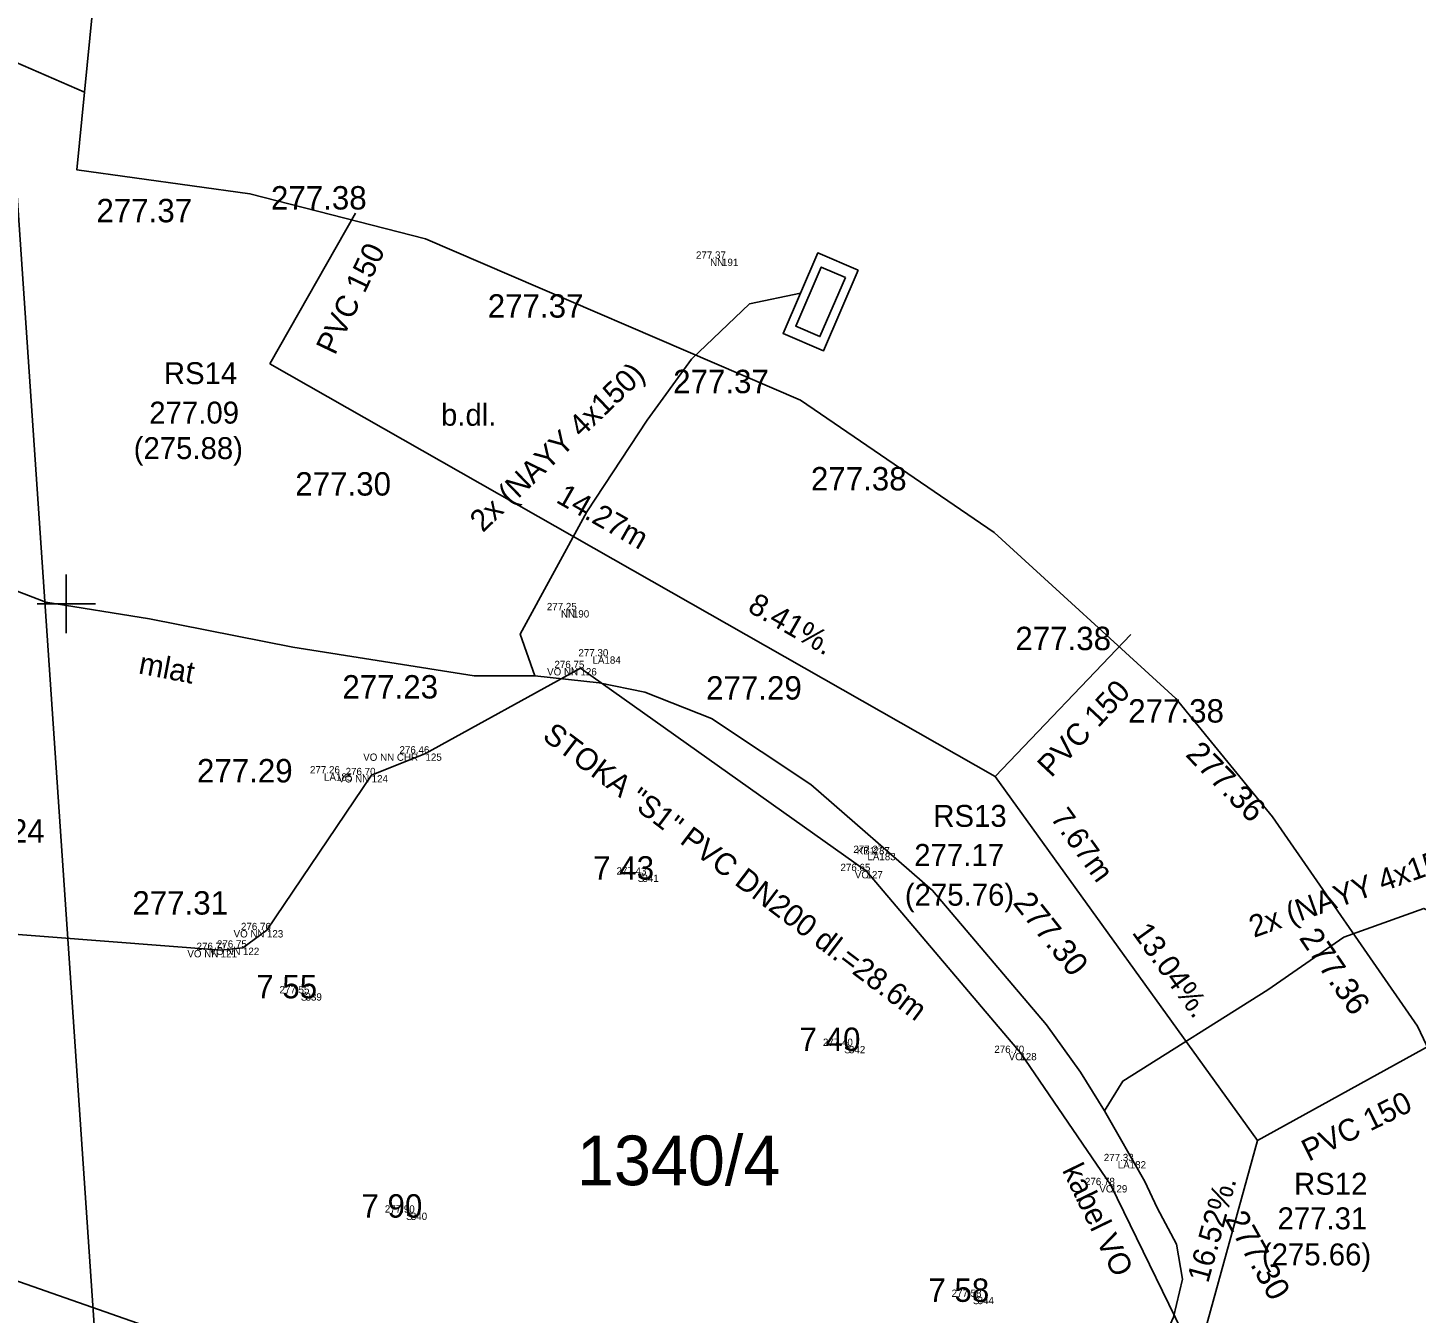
# Model space of a CAD drawing. Extents: x -601602 to -600882, y -1162594 to -1161950.
# Drawn here: x -601150.66 to -601126.92, y -1162087.13 to -1162065.15 of the extents above; entities that cross this region are included whole.
import ezdxf

# ---------------------------------------------------------------- set-up
doc = ezdxf.new("R2010")
doc.units = 0
for name, color, linetype in [('BODY', 7, 'Continuous'), ('BODY_CISLA', 7, 'Continuous'), ('BODY_KODY', 7, 'Continuous'), ('BODY_VYSKY_CELE', 7, 'Continuous'), ('G_TEXTY', 7, 'Continuous'), ('H_KOTY_VYSKOVE', 7, 'Continuous'), ('H_VYSKY_PREVZATE', 7, 'Continuous'), ('IS_EON_NN', 7, 'Continuous'), ('IS_KAN_SPLASKOVA', 7, 'Continuous'), ('IS_VO', 7, 'Continuous'), ('IS_VO_AREAL', 7, 'Continuous'), ('KN_Hranice parcel', 7, 'Continuous'), ('KN_Parcelní čísla', 7, 'Continuous'), ('X_SOUR_KRIZKY_SEVER', 7, 'Continuous')]:
    doc.layers.add(name, color=color, linetype=linetype)

# ---------------------------------------------------------------- blocks, each defined once
blk = doc.blocks.new('POINT_DISPLAY')
blk.add_line((0, 0), (0, 0))
blk = doc.blocks.new('132_9')
at = {"layer": 'IS_EON_NN'}
for points in [[(-1.5, 1.5), (1.5, 1.5), (1.5, 0), (-1.5, 0)], [(-1.1, 1.2), (1.1, 1.2), (1.1, 0.3), (-1.1, 0.3)]]:
    blk.add_lwpolyline(points, close=True, dxfattribs=at)

msp = doc.modelspace()

# ---------------------------------------------------------------- linework, layer by layer
at = {"layer": 'IS_EON_NN'}
for points in [[(-601156.45, -1162065.9), (-601156.46, -1162066.9), (-601156.74, -1162069.72), (-601157.04, -1162071.88), (-601156.69, -1162072.3), (-601155.65, -1162072.6), (-601154.16, -1162073.09), (-601152, -1162074.34), (-601150.35, -1162074.97), (-601148.58, -1162075.26), (-601146.13, -1162075.74), (-601143.03, -1162076.23), (-601141.99, -1162076.23)], [(-601141.99, -1162076.23), (-601142.24, -1162075.52), (-601141.1, -1162073.43), (-601140.07, -1162071.86), (-601139.31, -1162070.82), (-601138.32, -1162069.87), (-601137.45, -1162069.69)], [(-601132.25, -1162083.67), (-601132.66, -1162083.01), (-601133.24, -1162082.2), (-601135.19, -1162079.9), (-601137.27, -1162078.09), (-601138.97, -1162076.96), (-601140.11, -1162076.51), (-601140.89, -1162076.35), (-601141.99, -1162076.23)], [(-601132.25, -1162083.67), (-601131.94, -1162083.16), (-601129.46, -1162081.6), (-601128.16, -1162080.7), (-601126.79, -1162080.21), (-601125.98, -1162080.61)], [(-601132.25, -1162083.67), (-601131.56, -1162084.88), (-601131.35, -1162085.33), (-601131.02, -1162085.95), (-601130.92, -1162086.55), (-601131.07, -1162087.2), (-601132.61, -1162090.6), (-601133.2, -1162092.06), (-601133.29, -1162092.54), (-601133.09, -1162093.04), (-601132.66, -1162093.44), (-601128.6, -1162095.14), (-601128.04, -1162095.48)]]:
    msp.add_lwpolyline(points, dxfattribs=at)
at = {"layer": 'IS_KAN_SPLASKOVA'}
for p, q in [((-601146.52, -1162070.896), (-601145.055, -1162068.32)), ((-601131.802, -1162075.528), (-601134.119, -1162077.951)), ((-601126.484, -1162082.438), (-601129.637, -1162084.177))]:
    msp.add_line(p, q, dxfattribs=at)
msp.add_lwpolyline([(-601131.407, -1162090.599), (-601129.637, -1162084.177), (-601134.119, -1162077.951), (-601146.52, -1162070.896)], dxfattribs=at)
at = {"layer": 'IS_VO'}
msp.add_lwpolyline([(-601158.666, -1162083.84), (-601145.3, -1162088.52), (-601144.81, -1162089.24), (-601144.157, -1162088.925), (-601135.38, -1162092.04), (-601131.27, -1162093.86), (-601131.18, -1162093.85), (-601130.74, -1162094.17), (-601128.82, -1162095.1), (-601124.26, -1162100.28), (-601123.56, -1162100.82), (-601122.79, -1162101.34), (-601121.45, -1162102.28), (-601119.91, -1162102.84), (-601117.99, -1162103.55), (-601114.43, -1162104.44), (-601112.91, -1162104.68), (-601111.96, -1162104.83), (-601105.22, -1162106.94), (-601104.99, -1162107.32)], dxfattribs=at)
at = {"layer": 'IS_VO_AREAL'}
msp.add_lwpolyline([(-601151.27, -1162080.62), (-601147.36, -1162080.92), (-601146.98, -1162080.88), (-601146.57, -1162080.58), (-601144.78, -1162077.93), (-601143.86, -1162077.56), (-601141.21, -1162076.1), (-601136.32, -1162079.57), (-601133.69, -1162082.68), (-601132.14, -1162084.94), (-601130.6, -1162088.11), (-601130.19, -1162090.08), (-601131.12, -1162093.43), (-601131.18, -1162093.85)], dxfattribs=at)
at = {"layer": 'KN_Hranice parcel'}
for p in [(-601149.69, -1162066.25), (-601149.45, -1162088.38)]:
    msp.add_line(p, (-601151, -1162065.68), dxfattribs=at)
for points in [[(-601149.69, -1162066.25), (-601147.49, -1162043.97), (-601144.7, -1162044.26), (-601138.75, -1162045.48), (-601133.58, -1162047.15), (-601128.54, -1162049.35), (-601123.75, -1162052.06), (-601119.34, -1162055.16), (-601115.08, -1162058.98), (-601111.36, -1162063.04), (-601108.08, -1162067.46), (-601105.25, -1162072.3), (-601104.9, -1162073.07)], [(-601104.9, -1162073.07), (-601103.03, -1162077.23), (-601101.26, -1162082.55), (-601100.06, -1162087.92), (-601099.46, -1162093.3), (-601099.43, -1162099.35), (-601099.69, -1162102.16), (-601123.33, -1162099.81), (-601123.14, -1162096.25), (-601123.49, -1162092.41), (-601123.92, -1162089.87), (-601125.19, -1162085.83), (-601126.9, -1162082.22), (-601129.38, -1162078.64), (-601131.03, -1162076.62), (-601134.14, -1162073.78), (-601137.45, -1162071.52), (-601143.86, -1162068.76), (-601146.86, -1162067.99), (-601149.82, -1162067.58), (-601149.69, -1162066.25)]]:
    msp.add_lwpolyline(points, dxfattribs=at)
at = {"layer": 'X_SOUR_KRIZKY_SEVER'}
for p, q in [((-601150, -1162075.5), (-601150, -1162074.5)), ((-601150.5, -1162075), (-601149.5, -1162075))]:
    msp.add_line(p, q, dxfattribs=at)

# ---------------------------------------------------------------- block references
at = {"layer": 'BODY'}
for p in [(-601138.79, -1162069.1), (-601141.34, -1162075.11), (-601140.8, -1162075.9), (-601141.21, -1162076.1), (-601143.86, -1162077.56), (-601145.39, -1162077.9), (-601144.78, -1162077.93), (-601136.2, -1162079.16), (-601136.1, -1162079.26), (-601140.15, -1162079.63), (-601136.32, -1162079.57), (-601146.57, -1162080.58), (-601147.36, -1162080.92), (-601146.98, -1162080.88), (-601145.91, -1162081.66), (-601136.62, -1162082.56), (-601133.69, -1162082.68), (-601131.82, -1162084.53), (-601132.14, -1162084.94), (-601144.11, -1162085.41), (-601134.42, -1162086.85)]:
    msp.add_blockref('POINT_DISPLAY', p, dxfattribs=at)
at = {"layer": 'IS_EON_NN', "xscale": 0.5, "yscale": 0.5, "rotation": -113.29561055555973}
msp.add_blockref('132_9', (-601137.45, -1162069.69), dxfattribs=at)

# ---------------------------------------------------------------- texts
at = {"layer": 'BODY_CISLA'}
for s, p in [('191', (-601138.79, -1162069.225)), ('190', (-601141.34, -1162075.235)), ('184', (-601140.8, -1162076.025)), ('126', (-601141.21, -1162076.225)), ('125', (-601143.86, -1162077.685)), ('185', (-601145.39, -1162078.025)), ('124', (-601144.78, -1162078.055)), ('237', (-601136.2, -1162079.285)), ('183', (-601136.1, -1162079.385)), ('341', (-601140.15, -1162079.755)), ('127', (-601136.32, -1162079.695)), ('123', (-601146.57, -1162080.705)), ('121', (-601147.36, -1162081.045)), ('122', (-601146.98, -1162081.005)), ('339', (-601145.91, -1162081.785)), ('342', (-601136.62, -1162082.685)), ('128', (-601133.69, -1162082.805)), ('182', (-601131.82, -1162084.655)), ('129', (-601132.14, -1162085.065)), ('340', (-601144.11, -1162085.535)), ('344', (-601134.42, -1162086.975))]:
    msp.add_text(s, height=0.125, dxfattribs=at).set_placement(p)
at = {"layer": 'BODY_KODY'}
for s, p in [('NN', (-601138.994, -1162069.225)), ('NN', (-601141.544, -1162075.235)), ('LA', (-601141.004, -1162076.025)), ('VO NN', (-601141.78, -1162076.225)), ('VO NN CHR', (-601144.924, -1162077.685)), ('LA', (-601145.594, -1162078.025)), ('VO NN', (-601145.35, -1162078.055)), ('KB1', (-601136.486, -1162079.285)), ('LA', (-601136.304, -1162079.385)), ('S', (-601140.231, -1162079.755)), ('VO', (-601136.519, -1162079.695)), ('VO NN', (-601147.14, -1162080.705)), ('VO NN', (-601147.93, -1162081.045)), ('VO NN', (-601147.55, -1162081.005)), ('S', (-601145.991, -1162081.785)), ('S', (-601136.701, -1162082.685)), ('VO', (-601133.889, -1162082.805)), ('LA', (-601132.024, -1162084.655)), ('VO', (-601132.339, -1162085.065)), ('S', (-601144.191, -1162085.535)), ('S', (-601134.501, -1162086.975))]:
    msp.add_text(s, height=0.125, dxfattribs=at).set_placement(p)
at = {"layer": 'BODY_VYSKY_CELE'}
for s, p in [('277.37 ', (-601139.235, -1162069.1)), ('277.25 ', (-601141.785, -1162075.11)), ('276.75 ', (-601141.655, -1162076.1)), ('277.30 ', (-601141.245, -1162075.9)), ('276.46 ', (-601144.304, -1162077.56)), ('277.26 ', (-601145.834, -1162077.9)), ('276.70 ', (-601145.225, -1162077.93)), ('277.27 ', (-601136.545, -1162079.26)), ('277.43 ', (-601140.593, -1162079.63)), ('276.65 ', (-601136.765, -1162079.57)), ('276.76 ', (-601147.014, -1162080.58)), ('276.71 ', (-601147.772, -1162080.92)), ('276.75 ', (-601147.425, -1162080.88)), ('277.55 ', (-601146.355, -1162081.66)), ('277.40 ', (-601137.065, -1162082.56)), ('276.70 ', (-601134.135, -1162082.68)), ('277.33 ', (-601132.263, -1162084.53)), ('276.78 ', (-601132.585, -1162084.94)), ('277.90 ', (-601144.555, -1162085.41)), ('277.58 ', (-601134.865, -1162086.85))]:
    msp.add_text(s, height=0.125, dxfattribs=at).set_placement(p)
at = {"layer": 'G_TEXTY'}
msp.add_text('b.dl.', height=0.375, dxfattribs=at).set_placement((-601143.594, -1162071.956))
msp.add_text('b.dl.', height=0.375, dxfattribs=at).set_placement((-601143.594, -1162071.956))
msp.add_text('mlat', height=0.375, rotation=349.1372, dxfattribs=at).set_placement((-601148.78, -1162076.189))
at = {"layer": 'H_KOTY_VYSKOVE'}
for s, p in [(' 7 43', (-601141.141, -1162079.716)), (' 7 55', (-601146.901, -1162081.746)), (' 7 40', (-601137.613, -1162082.646)), (' 7 90', (-601145.103, -1162085.496)), (' 7 58', (-601135.411, -1162086.936))]:
    msp.add_text(s, height=0.4, dxfattribs=at).set_placement(p)
at = {"layer": 'H_VYSKY_PREVZATE'}
for s, p in [('277.38', (-601146.501, -1162068.259)), ('277.37', (-601149.485, -1162068.477)), ('277.37', (-601142.795, -1162070.108)), ('277.37', (-601139.625, -1162071.399)), ('277.38', (-601137.27, -1162073.062)), ('277.30', (-601146.085, -1162073.15)), ('277.38', (-601133.775, -1162075.793)), ('277.23', (-601145.28, -1162076.62)), ('277.29', (-601139.062, -1162076.638)), ('277.38', (-601131.845, -1162077.031)), ('277.29', (-601147.766, -1162078.054)), ('277.24', (-601152.005, -1162079.083)), ('277.31', (-601148.871, -1162080.314))]:
    msp.add_text(s, height=0.4, dxfattribs=at).set_placement(p)
for s, rotation, p in [('277.36 ', 314.1736, (-601130.883, -1162077.591)), ('277.30 ', 308.5355, (-601133.83, -1162080.121)), ('277.36 ', 304.1785, (-601128.935, -1162080.713)), ('277.30 ', 299.1977, (-601130.203, -1162085.517))]:
    msp.add_text(s, height=0.4, rotation=rotation, dxfattribs=at).set_placement(p)
at = {"layer": 'IS_EON_NN'}
for rotation, p in [(43.8188, (-601142.88, -1162073.793)), (19.6803, (-601129.697, -1162080.713))]:
    msp.add_text('2x (NAYY 4x150)', height=0.375, rotation=rotation, dxfattribs=at).set_placement(p)
at = {"layer": 'IS_KAN_SPLASKOVA'}
for s, rotation, p in [('PVC 150', 64.4482, (-601145.407, -1162070.764)), ('14.27m', 330.3642, (-601141.646, -1162073.256)), ('8.41%.', 330.3642, (-601138.372, -1162075.121)), ('PVC 150', 46.8404, (-601133.16, -1162077.986)), ('STOKA "S1" PVC DN200 dl.=28.6m', 322.8907, (-601141.88, -1162077.303)), ('7.67m', 305.7495, (-601133.187, -1162078.662)), ('13.04%.', 305.7495, (-601131.791, -1162080.623)), ('PVC 150', 26.202, (-601128.761, -1162084.542)), ('16.52%.', 74.591, (-601130.48, -1162086.628))]:
    msp.add_text(s, height=0.375, rotation=rotation, dxfattribs=at).set_placement(p)
for s, p in [('RS14', (-601148.332, -1162071.245)), ('277.09', (-601148.581, -1162071.919)), ('(275.88)', (-601148.848, -1162072.526)), ('RS13', (-601135.178, -1162078.814)), ('277.17', (-601135.503, -1162079.482)), ('(275.76)', (-601135.664, -1162080.162)), ('RS12', (-601129.011, -1162085.104)), ('277.31', (-601129.293, -1162085.695)), ('(275.66)', (-601129.56, -1162086.312))]:
    msp.add_text(s, height=0.375, dxfattribs=at).set_placement(p)
at = {"layer": 'IS_VO_AREAL'}
msp.add_text('kabel VO', height=0.375, rotation=295.9107, dxfattribs=at).set_placement((-601132.982, -1162084.684))
at = {"layer": 'KN_Parcelní čísla'}
msp.add_text('1340/4', height=0.85, dxfattribs=at).set_placement((-601141.27, -1162084.942))

doc.saveas('drawing.dxf')
